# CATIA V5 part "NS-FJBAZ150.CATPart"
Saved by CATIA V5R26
Part number: NS-FJBAZ150
Bounding box of the stored display mesh (mm): x -60 to 120, y 0 to 198, z -110.177 to 60
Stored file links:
  R:\Document\坂尻\その他\ナベヤデータ変換\安全カバーキャスター\MCBJSZAZ150\NS-FJBAZ150.CATPart
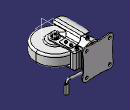
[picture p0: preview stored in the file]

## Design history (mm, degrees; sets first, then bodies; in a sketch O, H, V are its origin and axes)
Body1 (main body)
  Solid1: solid without history
  Body2
    Solid2: solid without history
  Assemble1: tool Body2
  Body3
    Solid3: solid without history
  Assemble2: tool Body3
